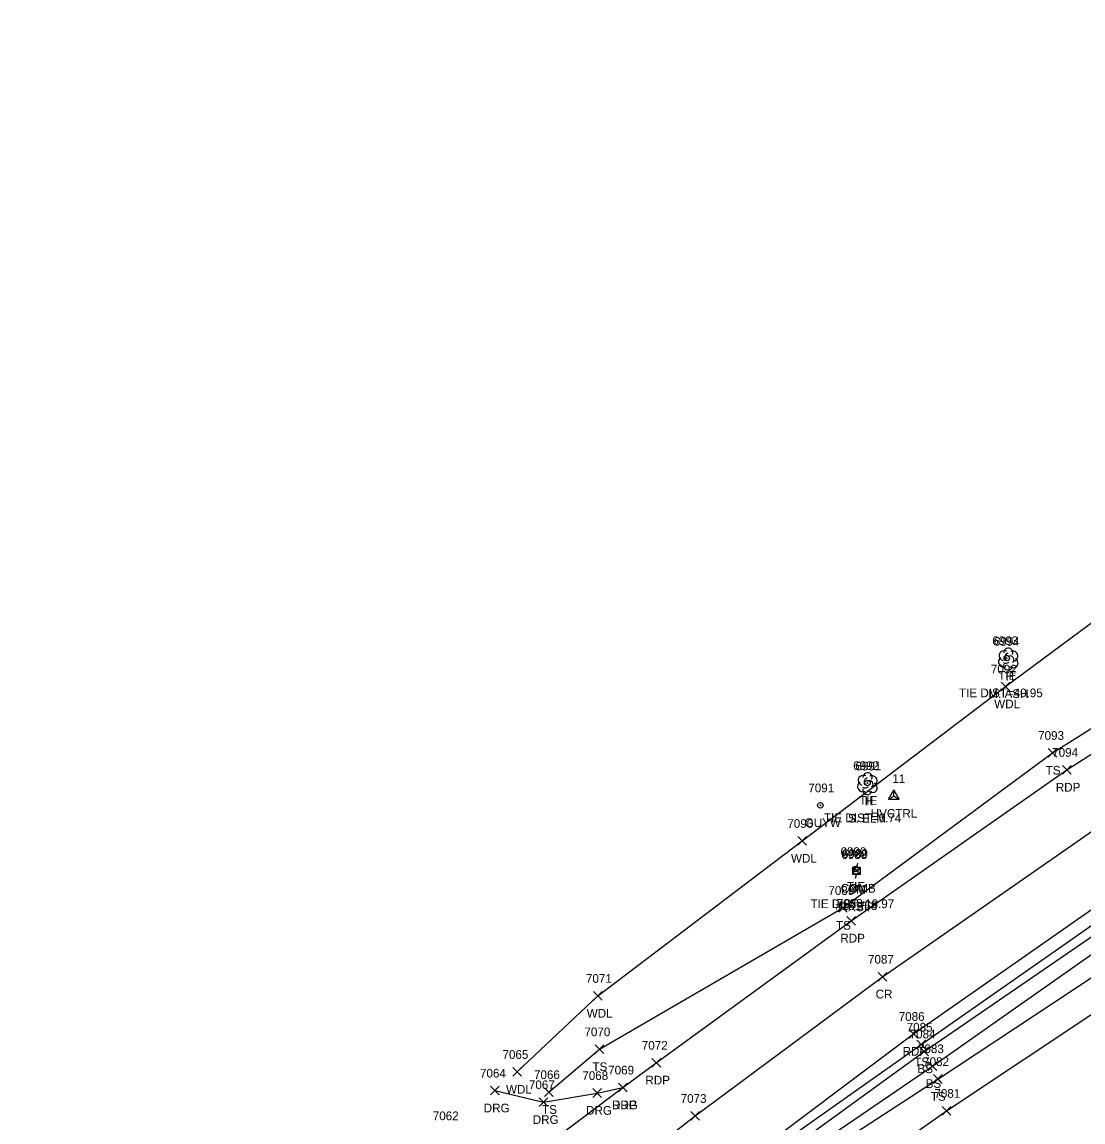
# Model space of a CAD drawing. Extents: x 1611797 to 1633212, y 298978 to 305475.
# Drawn here: x 1623974.4 to 1624218.3, y 304292 to 304544.9 of the extents above; entities that cross this region are included whole.
import ezdxf

# ---------------------------------------------------------------- set-up
doc = ezdxf.new("R2010")
doc.units = 0
for name, color, linetype in [('C_A', 7, 'Continuous'), ('C_C', 7, 'Continuous'), ('C_I', 7, 'Continuous'), ('CBP', 7, 'Continuous'), ('CPBM', 7, 'Continuous'), ('CPSM', 7, 'Continuous'), ('L_A', 7, 'Continuous'), ('L_C', 7, 'Continuous'), ('L_I', 7, 'Continuous'), ('L_TIC', 7, 'Continuous'), ('LAWA', 7, 'Continuous'), ('LELB', 7, 'Continuous'), ('LTD', 7, 'Continuous'), ('P_A', 7, 'Continuous'), ('P_I', 7, 'Continuous'), ('P_TIC', 7, 'Continuous'), ('PET', 7, 'Continuous'), ('PRC', 7, 'Continuous'), ('R_A', 7, 'Continuous'), ('R_I', 7, 'Continuous'), ('R_TIC', 7, 'Continuous'), ('RDG', 7, 'Continuous'), ('U_A', 7, 'Continuous'), ('U_C', 7, 'Continuous'), ('U_I', 7, 'Continuous'), ('UP', 7, 'Continuous'), ('UPGW', 7, 'Continuous')]:
    doc.layers.add(name, color=color, linetype=linetype)

msp = doc.modelspace()

# ---------------------------------------------------------------- linework, layer by layer
at = {"layer": 'CBP'}
for centre, radius in [((1624200.78, 304398.64), 0.625), ((1624200.78, 304398.64), 0.0833), ((1624168.8, 304369.91), 0.625), ((1624168.8, 304369.91), 0.0833), ((1624165.98, 304350.15), 0.625), ((1624165.98, 304350.15), 0.0833)]:
    msp.add_circle(centre, radius, dxfattribs=at)
at = {"layer": 'CPBM'}
for p, q in [((1624165.57, 304348.95), (1624165.57, 304349.95)), ((1624165.57, 304349.95), (1624166.57, 304349.95)), ((1624166.57, 304348.95), (1624165.57, 304348.95)), ((1624166.07, 304349.45), (1624166.07, 304349.45)), ((1624166.07, 304349.45), (1624166.07, 304349.45)), ((1624166.57, 304349.95), (1624166.57, 304348.95))]:
    msp.add_line(p, q, dxfattribs=at)
at = {"layer": 'CPSM'}
for p, q in [((1624173.59, 304366.21), (1624174.84, 304368.37)), ((1624176.09, 304366.21), (1624174.84, 304368.37)), ((1624174.84, 304366.93), (1624174.84, 304368.37)), ((1624173.59, 304366.21), (1624174.84, 304366.93)), ((1624173.59, 304366.21), (1624176.09, 304366.21)), ((1624174.84, 304366.93), (1624174.84, 304366.93)), ((1624174.84, 304366.93), (1624176.09, 304366.21))]:
    msp.add_line(p, q, dxfattribs=at)
at = {"layer": 'L_TIC'}
for points in [[(1624199.5, 304391.1), (1624201.5, 304393.1)], [(1624201.5, 304391.1), (1624199.5, 304393.1)], [(1624210.36, 304375.85), (1624212.36, 304377.85)], [(1624212.36, 304375.85), (1624210.36, 304377.85)], [(1624152.79, 304355.6), (1624154.79, 304357.6)], [(1624154.79, 304355.6), (1624152.79, 304357.6)], [(1624162.15, 304340.2), (1624164.15, 304342.2)], [(1624164.15, 304340.2), (1624162.15, 304342.2)], [(1624105.81, 304319.98), (1624107.81, 304321.98)], [(1624107.81, 304319.98), (1624105.81, 304321.98)], [(1624180.13, 304308.78), (1624182.13, 304310.78)], [(1624182.13, 304308.78), (1624180.13, 304310.78)], [(1624106.13, 304307.7), (1624108.13, 304309.7)], [(1624108.13, 304307.7), (1624106.13, 304309.7)], [(1624180.83, 304307.22), (1624182.83, 304309.22)], [(1624182.83, 304307.22), (1624180.83, 304309.22)], [(1624182.73, 304303.83), (1624184.73, 304305.83)], [(1624184.73, 304303.83), (1624182.73, 304305.83)], [(1624087.25, 304302.5), (1624089.25, 304304.5)], [(1624089.25, 304302.5), (1624087.25, 304304.5)], [(1624183.93, 304300.87), (1624185.93, 304302.87)], [(1624185.93, 304300.87), (1624183.93, 304302.87)], [(1624094.54, 304297.86), (1624096.54, 304299.86)], [(1624096.54, 304297.86), (1624094.54, 304299.86)], [(1624185.93, 304293.55), (1624187.93, 304295.55)], [(1624187.93, 304293.55), (1624185.93, 304295.55)]]:
    msp.add_lwpolyline(points, dxfattribs=at)
at = {"layer": 'LAWA'}
for points in [[(1624088.25, 304303.5), (1624106.81, 304320.98), (1624153.79, 304356.6), (1624200.5, 304392.1), (1624247.6, 304427), (1624285.25, 304446.91), (1624325.08, 304470.25), (1624369.06, 304488.79), (1624425.3, 304516.01), (1624470.84, 304531.32), (1624503.11, 304542.37)], [(1623820.79, 303877.68), (1623816.25, 303882.45), (1623845.39, 303933.13), (1623868.52, 303966.33), (1623895.88, 304001.62), (1623916.89, 304037.42), (1623938.51, 304074.19), (1623964.42, 304107.21), (1624004.64, 304144.93), (1624031.16, 304170.25), (1624074.89, 304204.59), (1624093.25, 304225.45), (1624128.84, 304248.67), (1624153.26, 304270.75), (1624186.93, 304294.55), (1624240.75, 304330.36)]]:
    msp.add_lwpolyline(points, dxfattribs=at)
at = {"layer": 'LELB'}
for points in [[(1624095.54, 304298.86), (1624107.13, 304308.7), (1624163.15, 304341.2), (1624211.36, 304376.85), (1624256.11, 304405.01), (1624295.12, 304429.63), (1624332.27, 304455.09), (1624374.78, 304478.34), (1624401.92, 304484.81), (1624434.05, 304498.5), (1624472.98, 304511.84), (1624506.38, 304522.93), (1624552.27, 304533.91), (1624584.91, 304535.68), (1624625.23, 304538.42), (1624653.95, 304544.88), (1624697.41, 304542.2), (1624744.04, 304535.67), (1624782.56, 304529.52), (1624820.4, 304520.29), (1624849.23, 304510.65), (1624882.95, 304501.96), (1624884.04, 304505.26)], [(1624083.58, 304227.76), (1624087.42, 304228.59), (1624118.97, 304253.32), (1624144.2, 304275.29), (1624184.93, 304301.87), (1624278.34, 304363.53)], [(1624081.07, 304230.9), (1624082.23, 304233.74), (1624104.56, 304251.96), (1624139.65, 304280.53), (1624181.13, 304309.78), (1624231.77, 304345.18)], [(1624083.84, 304228.86), (1624105.8, 304250.27), (1624141.05, 304278.64), (1624181.83, 304308.22), (1624233.12, 304343.37)], [(1624083.84, 304228.86), (1624106.94, 304248.51), (1624142.5, 304276.67), (1624183.73, 304304.83), (1624234.53, 304340.54)]]:
    msp.add_lwpolyline(points, dxfattribs=at)
at = {"layer": 'LTD'}
for p, q in [((1624201.13, 304398.47), (1624201.13, 304398.47)), ((1624201.13, 304398.47), (1624201.13, 304398.47)), ((1624168.75, 304369.81), (1624168.75, 304369.81)), ((1624168.75, 304369.81), (1624168.75, 304369.81))]:
    msp.add_line(p, q, dxfattribs=at)
for centre in [(1624201.18, 304399.9), (1624168.79, 304371.24)]:
    msp.add_arc(centre, 1.05, 335.5272, 180.9563, dxfattribs=at)
for centre, major_axis, ratio, start_param, end_param in [((1624200.05, 304397.76), (0.58, -1.04), 0.959034, 3.141593, 6.283185), ((1624200.34, 304399.14), (1.21, -0.51), 0.895232, 1.570796, 4.712389), ((1624200.92, 304398.93), (-0.208, -0.792), 0.645439, 3.141593, 6.283185), ((1624201.63, 304398.3), (-0.5, 0.667), 0.989748, 3.141593, 6.283185), ((1624202.13, 304397.64), (-1.09, 0.79), 0.841452, 1.570796, 4.712389), ((1624202.17, 304399.05), (-1.14, -0.48), 0.949671, 1.570796, 4.712389), ((1624201.13, 304396.97), (0.26, 1.06), 0.942809, 1.570796, 4.712389), ((1624200.67, 304397.72), (-0.625, -0.083), 0.423636, 0, 3.141593), ((1624167.95, 304370.47), (1.21, -0.51), 0.895232, 1.570796, 4.712389), ((1624168.54, 304370.26), (-0.208, -0.792), 0.645439, 3.141593, 6.283185), ((1624169.25, 304369.64), (-0.5, 0.667), 0.989748, 3.141593, 6.283185), ((1624169.79, 304370.39), (-1.14, -0.48), 0.949671, 1.570796, 4.712389), ((1624167.66, 304369.1), (0.58, -1.04), 0.959034, 3.141593, 6.283185), ((1624168.75, 304368.31), (0.26, 1.06), 0.942809, 1.570796, 4.712389), ((1624168.29, 304369.06), (-0.625, -0.083), 0.423636, 0, 3.141593), ((1624169.75, 304368.97), (-1.09, 0.79), 0.841452, 1.570796, 4.712389)]:
    msp.add_ellipse(centre, major_axis=major_axis, ratio=ratio, start_param=start_param, end_param=end_param, dxfattribs=at)
at = {"layer": 'P_TIC'}
for points in [[(1624213.6, 304371.95), (1624215.6, 304373.95)], [(1624215.6, 304371.95), (1624213.6, 304373.95)], [(1624164.06, 304337.25), (1624166.06, 304339.25)], [(1624166.06, 304337.25), (1624164.06, 304339.25)], [(1624171.24, 304324.39), (1624173.24, 304326.39)], [(1624173.24, 304324.39), (1624171.24, 304326.39)], [(1624178.36, 304311.24), (1624180.36, 304313.24)], [(1624180.36, 304311.24), (1624178.36, 304313.24)], [(1624119.23, 304304.61), (1624121.23, 304306.61)], [(1624121.23, 304304.61), (1624119.23, 304306.61)], [(1624111.56, 304298.92), (1624113.56, 304300.92)], [(1624113.56, 304298.92), (1624111.56, 304300.92)], [(1624128.15, 304292.39), (1624130.15, 304294.39)], [(1624130.15, 304292.39), (1624128.15, 304294.39)]]:
    msp.add_lwpolyline(points, dxfattribs=at)
at = {"layer": 'PET'}
for points in [[(1623734.72, 303818.72), (1623741.35, 303832.79), (1623751.88, 303855.21), (1623768.06, 303888.23), (1623783.81, 303919.21), (1623803.8, 303953.17), (1623823.4, 303986.78), (1623844.63, 304021.43), (1623861.98, 304047.29), (1623874.41, 304064.9), (1623903.88, 304103.57), (1623926.42, 304130.92), (1623968.84, 304177.26), (1623998.66, 304205.49), (1624036.82, 304239.77), (1624084.71, 304279.03), (1624112.56, 304299.92), (1624120.23, 304305.61), (1624165.06, 304338.25), (1624214.6, 304372.95), (1624258.69, 304401.17)], [(1623753.98, 303796.37), (1623772.12, 303834.51), (1623792.43, 303875.75), (1623808.26, 303904.51), (1623828.44, 303938.4), (1623847.99, 303970.88), (1623878.6, 304016.89), (1623898.4, 304046.12), (1623927.58, 304084.75), (1623950.31, 304112.67), (1623990.12, 304155.59), (1624018.08, 304183.31), (1624056.52, 304216.58), (1624078.27, 304234.86), (1624102.63, 304254.08), (1624138.53, 304281.62), (1624179.36, 304312.24), (1624229.96, 304347.62)]]:
    msp.add_lwpolyline(points, dxfattribs=at)
at = {"layer": 'PRC'}
msp.add_lwpolyline([(1623741.55, 303802.02), (1623760.52, 303841.05), (1623780.51, 303881.51), (1623815.97, 303945.98), (1623835.49, 303978.53), (1623866.25, 304025.48), (1623886.62, 304054.99), (1623916.18, 304093.56), (1623939.04, 304122.75), (1623980.27, 304165.88), (1624008.94, 304194.69), (1624046.78, 304227.75), (1624094.29, 304266.19), (1624129.15, 304293.39), (1624172.24, 304325.39), (1624222.29, 304360.15)], dxfattribs=at)
at = {"layer": 'R_TIC'}
for points in [[(1624082.07, 304298.2), (1624084.07, 304300.2)], [(1624084.07, 304298.2), (1624082.07, 304300.2)], [(1624111.56, 304298.92), (1624113.56, 304300.92)], [(1624113.56, 304298.92), (1624111.56, 304300.92)], [(1624093.32, 304295.54), (1624095.32, 304297.54)], [(1624095.32, 304295.54), (1624093.32, 304297.54)], [(1624105.6, 304297.65), (1624107.6, 304299.65)], [(1624107.6, 304297.65), (1624105.6, 304299.65)]]:
    msp.add_lwpolyline(points, dxfattribs=at)
at = {"layer": 'RDG'}
msp.add_lwpolyline([(1624083.07, 304299.2), (1624094.32, 304296.54), (1624106.6, 304298.65), (1624112.56, 304299.92)], dxfattribs=at)
at = {"layer": 'UP'}
for p, q in [((1624165.44, 304348.88), (1624165.44, 304350.55)), ((1624165.44, 304350.55), (1624167.11, 304350.55)), ((1624166.52, 304351.38), (1624166.27, 304350.55)), ((1624167.11, 304350.55), (1624167.11, 304348.88)), ((1624167.11, 304348.88), (1624165.44, 304348.88)), ((1624166.02, 304348.05), (1624166.27, 304348.88)), ((1624166.27, 304349.71), (1624166.27, 304349.71))]:
    msp.add_line(p, q, dxfattribs=at)
msp.add_circle((1624166.27, 304349.71), 0.833, dxfattribs=at)
at = {"layer": 'UPGW'}
for radius in [0.625, 0.0833]:
    msp.add_circle((1624157.95, 304364.79), radius, dxfattribs=at)

# ---------------------------------------------------------------- texts
at = {"layer": 'C_A'}
for s, p in [('TIE', (1624198.86, 304393.64)), ('TIE', (1624166.88, 304364.91)), ('HVCTRL', (1624169.53, 304361.93)), ('TIE', (1624164.06, 304345.15)), ('BM', (1624164.39, 304344.45))]:
    msp.add_text(s, height=2, dxfattribs=at).set_placement(p)
at = {"layer": 'C_C'}
for s, p in [('TIE DIST=40.95', (1624189.84, 304389.64)), ('TIE DIST=6.74', (1624158.78, 304360.91)), ('TIE DIST=18.97', (1624155.68, 304341.15)), ('RRSIP', (1624162.29, 304340.45))]:
    msp.add_text(s, height=2, dxfattribs=at).set_placement(p)
at = {"layer": 'C_I'}
for s, p in [('6993', (1624197.48, 304401.64)), ('6992', (1624165.49, 304372.91)), ('11', (1624174.51, 304369.93)), ('6990', (1624162.58, 304353.15)), ('6988', (1624162.77, 304352.45))]:
    msp.add_text(s, height=2, dxfattribs=at).set_placement(p)
at = {"layer": 'L_A'}
for s, p in [('H', (1624200.56, 304393.47)), ('WDL', (1624197.92, 304387.1)), ('TS', (1624209.77, 304371.85)), ('H', (1624168.18, 304364.81)), ('WDL', (1624151.2, 304351.6)), ('TS', (1624161.56, 304336.2)), ('WDL', (1624104.23, 304315.98)), ('TS', (1624105.54, 304303.7)), ('TS', (1624179.54, 304304.78)), ('BS', (1624180.27, 304303.22)), ('WDL', (1624085.67, 304298.5)), ('BS', (1624182.17, 304299.83)), ('TS', (1624183.34, 304296.87)), ('TS', (1624093.95, 304293.86))]:
    msp.add_text(s, height=2, dxfattribs=at).set_placement(p)
at = {"layer": 'L_C'}
for s, p in [('M. ASH', (1624196.59, 304389.47)), ('S. ELM', (1624164.29, 304360.81))]:
    msp.add_text(s, height=2, dxfattribs=at).set_placement(p)
at = {"layer": 'L_I'}
for s, p in [('6994', (1624197.82, 304401.47)), ('7092', (1624197.16, 304395.1)), ('7093', (1624208.02, 304379.85)), ('6991', (1624166, 304372.81)), ('7090', (1624150.36, 304359.6)), ('7089', (1624159.8, 304344.2)), ('7071', (1624104.04, 304323.98)), ('7070', (1624103.7, 304311.7)), ('7085', (1624177.8, 304312.78)), ('7084', (1624178.49, 304311.22)), ('7083', (1624180.39, 304307.83)), ('7065', (1624084.86, 304306.5)), ('7082', (1624181.59, 304304.87)), ('7066', (1624092.1, 304301.86)), ('7081', (1624184.16, 304297.55))]:
    msp.add_text(s, height=2, dxfattribs=at).set_placement(p)
at = {"layer": 'P_A'}
for s, p in [('RDP', (1624212.09, 304367.95)), ('RDP', (1624162.55, 304333.25)), ('CR', (1624170.67, 304320.39)), ('RDP', (1624176.85, 304307.24)), ('RDP', (1624117.72, 304300.61)), ('RDP', (1624110.04, 304294.92))]:
    msp.add_text(s, height=2, dxfattribs=at).set_placement(p)
at = {"layer": 'P_I'}
for s, p in [('7094', (1624211.26, 304375.95)), ('7088', (1624161.73, 304341.25)), ('7087', (1624168.9, 304328.39)), ('7086', (1624175.96, 304315.24)), ('7072', (1624116.89, 304308.61)), ('7069', (1624109.16, 304302.92)), ('7073', (1624125.82, 304296.39))]:
    msp.add_text(s, height=2, dxfattribs=at).set_placement(p)
at = {"layer": 'R_A'}
for p in [(1624080.55, 304294.2), (1624104.08, 304293.65), (1624110.04, 304294.92), (1624091.81, 304291.54)]:
    msp.add_text('DRG', height=2, dxfattribs=at).set_placement(p)
at = {"layer": 'R_I'}
for s, p in [('7069', (1624109.16, 304302.92)), ('7064', (1624079.68, 304302.2)), ('7068', (1624103.21, 304301.65)), ('7067', (1624090.93, 304299.54)), ('7062', (1624068.83, 304292.4))]:
    msp.add_text(s, height=2, dxfattribs=at).set_placement(p)
at = {"layer": 'U_A'}
for s, p in [('GUYW', (1624154.35, 304359.79)), ('COMB', (1624162.66, 304344.71))]:
    msp.add_text(s, height=2, dxfattribs=at).set_placement(p)
at = {"layer": 'U_C'}
msp.add_text('#181/58', height=2, dxfattribs=at).set_placement((1624161.38, 304340.71))
at = {"layer": 'U_I'}
for s, p in [('7091', (1624155.18, 304367.79)), ('6989', (1624162.96, 304352.71))]:
    msp.add_text(s, height=2, dxfattribs=at).set_placement(p)

doc.saveas('drawing.dxf')
